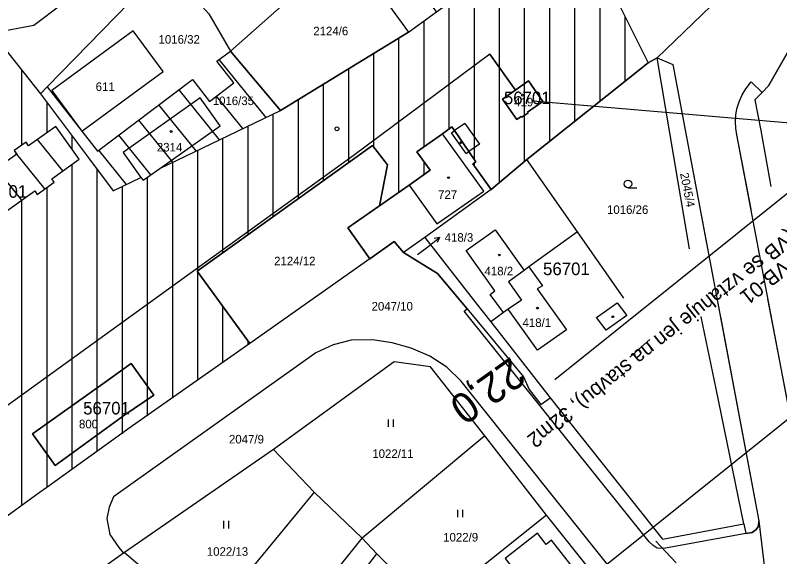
# Model space of a CAD drawing. Extents: x -794765 to -785424, y -1118958 to -1108731.
# Drawn here: x -792135.5 to -791983.5, y -1109804.8 to -1109697 of the extents above; entities that cross this region are included whole.
import ezdxf

# ---------------------------------------------------------------- set-up
doc = ezdxf.new("R2010")
doc.units = 0
for name, color, linetype in [('Level 66', 7, 'Continuous'), ('Level 71', 7, 'Continuous'), ('Level 73', 7, 'Continuous'), ('Level 75', 7, 'Continuous'), ('Level 76', 7, 'Continuous'), ('Level 77', 7, 'Continuous'), ('Level 78', 7, 'Continuous'), ('Level 79', 7, 'Continuous'), ('Level 80', 7, 'Continuous'), ('Level 81', 7, 'Continuous'), ('Vrstva 1', 7, 'Continuous'), ('Vrstva 53', 7, 'Continuous')]:
    doc.layers.add(name, color=color, linetype=linetype)

msp = doc.modelspace()

# ---------------------------------------------------------------- linework, layer by layer
at = {"layer": 'Level 66'}
for p, q in [((-792013.65, -1109731.34), (-792011.9, -1109731.34)), ((-792061.26, -1109778.93), (-792061.26, -1109777.43)), ((-792060.26, -1109778.93), (-792060.26, -1109777.43)), ((-792047.52, -1109796.9), (-792047.52, -1109795.4)), ((-792046.52, -1109796.9), (-792046.52, -1109795.4)), ((-792094.03, -1109799.12), (-792094.03, -1109797.62)), ((-792093.03, -1109799.12), (-792093.03, -1109797.62))]:
    msp.add_line(p, q, dxfattribs=at)
msp.add_circle((-792013.65, -1109730.59), 0.75, dxfattribs=at)
at = {"layer": 'Level 71'}
msp.add_lwpolyline([(-791938.08, -1109742.36), (-792598.01, -1110271.46), (-792786.15, -1110036.8), (-792126.22, -1109507.7)], close=True, dxfattribs=at)
at = {"layer": 'Level 75'}
for p, q in [((-792007.85, -1109705.47), (-791992.82, -1109691)), ((-791974.78, -1109691.82), (-791985.69, -1109711.05)), ((-792057.33, -1109700.37), (-792051.73, -1109696.36)), ((-792057.33, -1109700.37), (-792082.74, -1109715.97)), ((-792137.25, -1109704.07), (-792130.48, -1109712.65)), ((-792082.74, -1109715.97), (-792092.71, -1109704.13)), ((-792007.85, -1109705.47), (-792009.6, -1109706.46)), ((-792009.6, -1109706.46), (-792033.77, -1109725.73)), ((-791989.17, -1109710.28), (-791986.99, -1109712.39)), ((-792130.48, -1109712.65), (-792129.14, -1109711.27)), ((-791985.69, -1109711.05), (-791986.99, -1109712.39)), ((-792106.76, -1109727.49), (-792082.74, -1109715.97)), ((-791989.17, -1109735.63), (-791991.98, -1109720.83)), ((-792033.77, -1109725.73), (-792040.87, -1109731.66)), ((-792023.66, -1109740.13), (-792033.77, -1109725.73)), ((-792040.87, -1109731.66), (-792054.08, -1109741.21)), ((-792014.46, -1109753.3), (-792023.66, -1109740.13)), ((-792054.08, -1109741.21), (-792058.28, -1109744.24)), ((-792065.02, -1109745.49), (-792088.89, -1109762.3)), ((-791977.67, -1109796.24), (-791985.8, -1109753.42)), ((-791996.13, -1109771.37), (-791999.09, -1109757.03)), ((-792040.93, -1109758.03), (-792029.1, -1109773.17)), ((-792075.73, -1109764.16), (-792115.96, -1109792.85)), ((-791990.59, -1109798.22), (-791996.13, -1109771.37)), ((-792042.1, -1109780.72), (-792066.53, -1109801.07)), ((-792029.85, -1109796.46), (-792042.1, -1109780.72)), ((-792084.13, -1109783.45), (-792113.78, -1109803.9)), ((-792084.13, -1109783.45), (-792076.07, -1109791.91)), ((-792076.07, -1109791.91), (-792097.38, -1109817.76)), ((-792076.07, -1109791.91), (-792066.53, -1109801.07)), ((-792029.85, -1109796.46), (-792052.76, -1109814.79)), ((-792017.36, -1109812.14), (-792029.85, -1109796.46)), ((-791990.59, -1109798.22), (-791990.19, -1109800.13)), ((-791987.59, -1109797.65), (-791986.38, -1109808.14)), ((-791990.19, -1109800.13), (-792005.48, -1109802.95)), ((-792086.82, -1109826.3), (-792066.53, -1109801.07)), ((-792066.53, -1109801.07), (-792063.63, -1109804.17)), ((-792114.91, -1109802.94), (-792114.01, -1109804.07)), ((-792114.01, -1109804.07), (-792119.78, -1109808.18)), ((-792113.78, -1109803.9), (-792114.01, -1109804.07)), ((-792113.78, -1109803.9), (-792097.38, -1109817.76)), ((-792074.4, -1109818.02), (-792063.63, -1109804.17)), ((-792063.63, -1109804.17), (-792058.92, -1109808.77))]:
    msp.add_line(p, q, dxfattribs=at)
for points in [[(-792062.33, -1109677.36), (-792030.44, -1109685.15), (-792018.46, -1109688.78), (-792009.6, -1109706.46)], [(-792092.71, -1109704.13), (-792077.28, -1109690.45), (-792064.43, -1109679.2)], [(-792051.73, -1109696.36), (-792055.31, -1109691.31), (-792053.36, -1109689.93), (-792055.88, -1109686.41), (-792057.81, -1109687.78), (-792059.53, -1109685.37), (-792065.26, -1109689.44), (-792057.33, -1109700.37)], [(-792129.14, -1109711.27), (-792112.82, -1109694.46), (-792105.12, -1109689.46), (-792103.8, -1109689.27)], [(-792103.8, -1109689.27), (-792096.98, -1109696.76), (-792092.71, -1109704.13)], [(-792126.16, -1109694.83), (-792131.81, -1109699.06), (-792139.61, -1109700.53)], [(-792106.12, -1109708.23), (-792112.07, -1109700.09), (-792128.21, -1109711.96), (-792122.26, -1109720.08), (-792106.12, -1109708.23)], [(-792129.14, -1109711.27), (-792122.26, -1109720.08), (-792119.15, -1109724.06), (-792100.25, -1109709.81), (-792096.91, -1109714.15), (-792092.06, -1109710.49), (-792095.42, -1109706.17), (-792092.71, -1109704.13)], [(-792007.85, -1109705.47), (-792004.71, -1109706.83), (-791998.08, -1109742.02)], [(-792001.39, -1109743.48), (-792003.64, -1109730.21), (-792007.85, -1109705.47)], [(-792038.61, -1109713.71), (-792035.77, -1109717.77), (-792034.88, -1109717.16), (-792034.78, -1109717.31), (-792033.49, -1109716.43), (-792033.6, -1109716.27), (-792030.57, -1109714.17), (-792033.44, -1109710.08), (-792038.61, -1109713.71)], [(-791991.98, -1109720.83), (-791992.2, -1109719.5), (-791992.26, -1109718.2), (-791992.18, -1109716.87), (-791991.97, -1109715.65), (-791991.56, -1109714.23), (-791990.95, -1109712.85), (-791990.23, -1109711.63), (-791989.17, -1109710.28)], [(-792130.48, -1109712.65), (-792120.92, -1109725.39), (-792116.05, -1109731.95), (-792110.51, -1109729.29)], [(-792106.76, -1109727.49), (-792094.78, -1109719), (-792098.73, -1109713.45), (-792114.05, -1109724.35), (-792110.51, -1109729.29)], [(-791986.99, -1109712.39), (-791988.4, -1109713.84), (-791987.24, -1109719.97), (-791985.22, -1109731.09)], [(-792139.92, -1109727.96), (-792140.61, -1109726.97), (-792144.91, -1109730.01), (-792144.21, -1109731), (-792159.76, -1109741.99), (-792155.1, -1109748.67), (-792131.63, -1109731.96), (-792131.14, -1109732.66), (-792127.76, -1109730.25), (-792128.26, -1109729.56), (-792122.8, -1109725.68), (-792127.44, -1109719.13), (-792132.86, -1109722.97), (-792133.35, -1109722.27), (-792135.73, -1109723.95), (-792135.23, -1109724.65), (-792139.92, -1109727.96)], [(-792040.87, -1109731.66), (-792044.51, -1109726.58), (-792043.88, -1109726.16), (-792045.28, -1109724.14), (-792048.16, -1109719.98), (-792048.66, -1109719.25), (-792050.55, -1109720.58), (-792055.65, -1109724.16), (-792052.97, -1109727.83), (-792057.17, -1109730.8), (-792063.04, -1109734.91)], [(-792088.89, -1109762.3), (-792099.3, -1109747.92), (-792064.44, -1109722.94), (-792061.45, -1109726.78), (-792063.04, -1109734.91)], [(-792110.51, -1109729.29), (-792110.1, -1109729.86), (-792106.76, -1109727.49)], [(-792063.04, -1109734.91), (-792069.34, -1109739.32), (-792065.02, -1109745.49)], [(-792023.66, -1109740.13), (-792033.34, -1109747.1), (-792034.31, -1109747.79), (-792037.43, -1109750.08), (-792034.83, -1109753.69), (-792037.49, -1109755.5), (-792038.39, -1109756.14), (-792040.93, -1109758.03)], [(-792065.02, -1109745.49), (-792060.13, -1109742.03), (-792058.28, -1109744.24)], [(-792054.08, -1109741.21), (-792043.97, -1109754.14), (-792040.93, -1109758.03)], [(-792058.28, -1109744.24), (-792051.53, -1109748.38), (-792045.65, -1109755.46)], [(-792009.45, -1109801.79), (-792046.24, -1109755.92), (-792045.65, -1109755.46)], [(-792045.65, -1109755.46), (-792034.44, -1109768.97), (-792033.33, -1109771.51), (-792031.01, -1109774.5), (-792029.1, -1109773.17)], [(-791999.09, -1109757.03), (-791999.1, -1109756.95)], [(-791995.24, -1109757.05), (-791987.59, -1109797.65)], [(-791975.42, -1109863.21), (-791978.21, -1109857.78), (-791981.04, -1109853.58), (-792018.21, -1109805.69), (-792044.53, -1109772.76), (-792046.81, -1109769.82), (-792049.7, -1109767.06), (-792053.05, -1109764.88), (-792056.76, -1109763.28), (-792060.56, -1109762.21), (-792064.43, -1109761.57), (-792068.68, -1109761.68), (-792072.28, -1109762.62), (-792075.73, -1109764.16)], [(-792088.89, -1109762.3), (-792112.22, -1109778.74), (-792129.24, -1109790.96), (-792130.77, -1109792.06), (-792139.4, -1109798.31)], [(-792107.96, -1109772.62), (-792112.43, -1109766.33), (-792118.07, -1109770.33), (-792132.11, -1109780.3), (-792127.56, -1109786.58), (-792113.69, -1109776.53), (-792107.96, -1109772.62)], [(-792042.1, -1109780.72), (-792052.95, -1109766.96), (-792060.13, -1109766.01), (-792084.13, -1109783.45)], [(-792029.1, -1109773.17), (-792006.8, -1109801.29), (-791990.59, -1109798.22)], [(-792115.96, -1109792.85), (-792116.86, -1109794.88), (-792117.31, -1109797.12), (-792116.69, -1109800.34), (-792114.91, -1109802.94)], [(-791990.19, -1109800.13), (-791988.96, -1109799.96), (-791988.12, -1109799.35), (-791987.66, -1109798.67), (-791987.59, -1109797.65)], [(-792029.87, -1109815.6), (-792022.38, -1109809.77), (-792028.86, -1109801.47), (-792029.92, -1109802.3), (-792031.64, -1109800.09), (-792038.08, -1109805.1), (-792036.35, -1109807.31), (-792029.87, -1109815.6)], [(-792005.48, -1109802.95), (-792006.59, -1109803.15), (-792007.84, -1109803.07), (-792008.67, -1109802.54), (-792009.45, -1109801.79)]]:
    msp.add_lwpolyline(points, dxfattribs=at)
at = {"layer": 'Level 77'}
for p, q in [((-792046.11, -1109718.56), (-792048.16, -1109719.98)), ((-792046.11, -1109718.56), (-792043.21, -1109722.69)), ((-792042.35, -1109732.05), (-792050.55, -1109720.58)), ((-792048.75, -1109720.39), (-792048.16, -1109719.98)), ((-792045.84, -1109724.54), (-792048.75, -1109720.39)), ((-792043.21, -1109722.69), (-792045.28, -1109724.14)), ((-792045.84, -1109724.54), (-792045.28, -1109724.14)), ((-792057.17, -1109730.8), (-792051.69, -1109738.52)), ((-792051.69, -1109738.52), (-792042.35, -1109732.05)), ((-792045.81, -1109743.8), (-792040.07, -1109739.73)), ((-792040.07, -1109739.73), (-792034.31, -1109747.79)), ((-792040.1, -1109751.84), (-792045.81, -1109743.8)), ((-792033.34, -1109747.1), (-792030.63, -1109750.85)), ((-792030.63, -1109750.85), (-792031.74, -1109751.44)), ((-792031.74, -1109751.44), (-792025.88, -1109759.58)), ((-792041.08, -1109752.55), (-792040.1, -1109751.84)), ((-792038.39, -1109756.14), (-792041.08, -1109752.55)), ((-792019.89, -1109757.19), (-792015.77, -1109754.24)), ((-792015.77, -1109754.24), (-792013.86, -1109756.74)), ((-792031.67, -1109763.67), (-792037.49, -1109755.5)), ((-792017.98, -1109759.69), (-792019.89, -1109757.19)), ((-792013.86, -1109756.74), (-792017.98, -1109759.69)), ((-792025.88, -1109759.58), (-792031.67, -1109763.67)), ((-792009.29, -1109761.55), (-792013.29, -1109765.08))]:
    msp.add_line(p, q, dxfattribs=at)
at = {"layer": 'Level 78'}
for p, q in [((-792034.2, -1109726.09), (-792034.2, -1109684.23)), ((-792029.2, -1109722.09), (-792029.2, -1109685.53)), ((-792039.2, -1109730.27), (-792039.2, -1109687.2)), ((-792024.2, -1109718.1), (-792024.2, -1109687.04)), ((-792019.2, -1109714.11), (-792019.2, -1109688.56)), ((-792044.2, -1109725.7), (-792044.2, -1109690.83)), ((-792049.2, -1109719.63), (-792049.2, -1109694.47)), ((-792054.2, -1109723.14), (-792054.2, -1109698.1)), ((-792014.2, -1109710.13), (-792014.2, -1109697.28)), ((-792059.2, -1109732.22), (-792059.2, -1109701.52)), ((-792085.61, -1109717.35), (-792094.95, -1109705.82)), ((-792064.2, -1109723.25), (-792064.2, -1109704.59)), ((-792134.2, -1109722.87), (-792134.2, -1109707.94)), ((-792069.2, -1109726.35), (-792069.2, -1109707.66)), ((-792094.88, -1109721.79), (-792102.94, -1109711.84)), ((-792074.2, -1109729.93), (-792074.2, -1109710.73)), ((-792090.25, -1109719.57), (-792095.5, -1109713.09)), ((-792129.2, -1109720.38), (-792129.2, -1109714.36)), ((-792099.52, -1109724.02), (-792106.94, -1109714.85)), ((-792079.2, -1109733.52), (-792079.2, -1109713.8)), ((-792084.2, -1109737.1), (-792084.2, -1109716.67)), ((-792104.15, -1109726.24), (-792110.93, -1109717.86)), ((-792089.2, -1109740.68), (-792089.2, -1109719.07)), ((-792124.2, -1109723.7), (-792124.2, -1109721.02)), ((-792108.55, -1109728.76), (-792114.93, -1109720.88)), ((-792126.06, -1109727.99), (-792131.12, -1109721.74)), ((-792094.2, -1109744.27), (-792094.2, -1109721.47)), ((-792113.42, -1109730.69), (-792118.92, -1109723.89)), ((-792099.2, -1109747.85), (-792099.2, -1109723.86)), ((-792129.6, -1109731.56), (-792135.46, -1109724.32)), ((-792124.2, -1109787.39), (-792124.2, -1109726.67)), ((-792104.2, -1109773.18), (-792104.2, -1109726.26)), ((-792054.2, -1109728.7), (-792054.2, -1109726.15)), ((-792044.2, -1109727.01), (-792044.2, -1109726.37)), ((-792134.22, -1109733.8), (-792139.3, -1109727.53)), ((-792119.2, -1109783.84), (-792119.2, -1109727.71)), ((-792109.2, -1109776.73), (-792109.2, -1109729.22)), ((-792129.2, -1109790.94), (-792129.2, -1109731.28)), ((-792114.2, -1109780.29), (-792114.2, -1109731.06)), ((-792134.2, -1109794.54), (-792134.2, -1109733.79)), ((-792099.2, -1109769.63), (-792099.2, -1109748.06)), ((-792094.2, -1109766.07), (-792094.2, -1109754.96)), ((-792089.2, -1109762.52), (-792089.2, -1109761.87))]:
    msp.add_line(p, q, dxfattribs=at)
at = {"layer": 'Level 79'}
for centre in [(-792034.61, -1109712.91), (-792104.52, -1109720.15), (-792046.93, -1109722.38), (-792049.34, -1109729.33), (-792039.24, -1109744.72), (-792031.65, -1109755.29), (-792016.65, -1109757.01), (-792121.05, -1109774.88)]:
    msp.add_circle(centre, 0.175, dxfattribs=at)
at = {"layer": 'Level 80'}
for p, q in [((-792053.48, -1109743.08), (-792051.11, -1109741.23)), ((-792051.11, -1109741.23), (-792052.21, -1109741.45)), ((-792051.11, -1109741.23), (-792051.6, -1109742.24)), ((-792055.48, -1109744.64), (-792053.48, -1109743.08)), ((-792008.12, -1109801.63), (-792006.11, -1109803.8)), ((-792006.11, -1109803.8), (-792004.06, -1109806))]:
    msp.add_line(p, q, dxfattribs=at)
at = {"layer": 'Level 81'}
for points in [[(-791977.67, -1109796.24), (-791991.98, -1109720.83), (-791992.2, -1109719.5), (-791992.26, -1109718.2), (-791992.18, -1109716.87), (-791991.97, -1109715.65), (-791991.56, -1109714.23), (-791990.95, -1109712.85), (-791990.23, -1109711.63), (-791989.17, -1109710.28), (-791986.99, -1109712.39), (-791985.69, -1109711.05), (-791974.78, -1109691.82), (-791964.15, -1109675.11), (-791952.08, -1109657.83), (-791949.02, -1109652.63), (-791945.89, -1109647.32), (-791945.08, -1109645.94)], [(-792227.74, -1109767.63), (-792215.1, -1109759.26), (-792190.07, -1109741.13), (-792187.8, -1109739.49), (-792182.21, -1109735.57), (-792171.12, -1109727.8), (-792170.01, -1109729.04), (-792158.73, -1109719.12), (-792137.25, -1109704.07), (-792130.48, -1109712.65), (-792120.92, -1109725.39), (-792116.05, -1109731.95), (-792110.51, -1109729.29), (-792110.1, -1109729.86), (-792106.76, -1109727.49), (-792082.74, -1109715.97), (-792092.71, -1109704.13), (-792077.28, -1109690.45)], [(-792014.8, -1109810.08), (-792018.21, -1109805.69), (-792044.53, -1109772.76), (-792046.81, -1109769.82), (-792049.7, -1109767.06), (-792053.05, -1109764.88), (-792056.76, -1109763.28), (-792060.56, -1109762.21), (-792064.43, -1109761.57), (-792068.68, -1109761.68), (-792072.28, -1109762.62), (-792075.73, -1109764.16), (-792115.96, -1109792.85), (-792116.86, -1109794.88), (-792117.31, -1109797.12), (-792116.69, -1109800.34), (-792114.91, -1109802.94), (-792114.01, -1109804.07), (-792119.78, -1109808.18), (-792120.9, -1109806.8), (-792147.85, -1109825.45)]]:
    msp.add_lwpolyline(points, dxfattribs=at)
for points in [[(-792057.33, -1109700.37), (-792051.73, -1109696.36), (-792055.31, -1109691.31), (-792053.36, -1109689.93), (-792055.88, -1109686.41), (-792057.81, -1109687.78), (-792059.53, -1109685.37), (-792065.26, -1109689.44)], [(-792007.85, -1109705.47), (-792004.71, -1109706.83), (-791987.59, -1109797.65), (-791987.66, -1109798.67), (-791988.12, -1109799.35), (-791988.96, -1109799.96), (-791990.19, -1109800.13), (-792005.48, -1109802.95), (-792006.59, -1109803.15), (-792007.84, -1109803.07), (-792008.67, -1109802.54), (-792009.45, -1109801.79), (-792046.24, -1109755.92), (-792045.65, -1109755.46), (-792051.53, -1109748.38), (-792058.28, -1109744.24), (-792060.13, -1109742.03), (-792065.02, -1109745.49), (-792069.34, -1109739.32), (-792057.17, -1109730.8), (-792052.97, -1109727.83), (-792055.65, -1109724.16), (-792050.55, -1109720.58), (-792048.66, -1109719.25), (-792048.16, -1109719.98), (-792045.28, -1109724.14), (-792043.88, -1109726.16), (-792044.51, -1109726.58), (-792040.87, -1109731.66), (-792033.77, -1109725.73), (-792009.6, -1109706.46)], [(-792033.44, -1109710.08), (-792030.57, -1109714.17), (-792033.6, -1109716.27), (-792033.49, -1109716.43), (-792034.78, -1109717.31), (-792034.88, -1109717.16), (-792035.77, -1109717.77), (-792038.61, -1109713.71)], [(-792144.91, -1109730.01), (-792144.21, -1109731), (-792159.76, -1109741.99), (-792155.1, -1109748.67), (-792131.63, -1109731.96), (-792131.14, -1109732.66), (-792127.76, -1109730.25), (-792128.26, -1109729.56), (-792122.8, -1109725.68), (-792127.44, -1109719.13), (-792132.86, -1109722.97), (-792133.35, -1109722.27), (-792135.73, -1109723.95), (-792135.23, -1109724.65), (-792139.92, -1109727.96), (-792140.61, -1109726.97)], [(-792118.07, -1109770.33), (-792112.43, -1109766.33), (-792107.96, -1109772.62), (-792113.69, -1109776.53), (-792127.56, -1109786.58), (-792132.11, -1109780.3)]]:
    msp.add_lwpolyline(points, close=True, dxfattribs=at)
at = {"layer": 'Vrstva 1'}
for p, q in [((-792041.12, -1109704.75), (-792068.33, -1109725.02)), ((-792041.12, -1109704.75), (-792036.03, -1109711.9)), ((-791966.17, -1109719.81), (-792032.55, -1109714.08)), ((-791966.17, -1109719.81), (-792028.19, -1109769.53)), ((-792068.33, -1109725.02), (-792087.87, -1109739.13)), ((-792087.87, -1109739.13), (-792101.91, -1109749.26))]:
    msp.add_line(p, q, dxfattribs=at)
msp.add_lwpolyline([(-792036.03, -1109711.9), (-792041.12, -1109704.75), (-792068.33, -1109725.02), (-792101.91, -1109749.26), (-792182.09, -1109807.15)], dxfattribs=at)
msp.add_circle((-792071.53, -1109719.62), 0.375, dxfattribs=at)
at = {"layer": 'Vrstva 53'}
for points in [[(-792038.26, -1109686.52), (-792064.43, -1109679.2), (-792062.33, -1109677.36), (-792030.44, -1109685.15), (-792018.46, -1109688.78), (-792009.6, -1109706.46)], [(-792226.53, -1109766.83), (-792215.1, -1109759.26), (-792190.07, -1109741.13), (-792187.8, -1109739.49), (-792182.21, -1109735.57), (-792171.12, -1109727.8), (-792158.73, -1109719.12), (-792137.25, -1109704.07), (-792130.48, -1109712.65), (-792129.14, -1109711.27), (-792119.15, -1109724.06), (-792100.25, -1109709.81), (-792096.91, -1109714.15), (-792092.06, -1109710.49), (-792095.42, -1109706.17), (-792092.71, -1109704.13), (-792082.74, -1109715.97), (-792057.33, -1109700.37), (-792051.73, -1109696.36), (-792038.26, -1109686.52)], [(-792009.6, -1109706.46), (-792033.77, -1109725.73), (-792040.87, -1109731.66), (-792044.51, -1109726.58), (-792043.88, -1109726.16), (-792045.28, -1109724.14), (-792048.16, -1109719.98), (-792048.66, -1109719.25), (-792050.55, -1109720.58), (-792055.65, -1109724.16), (-792052.97, -1109727.83), (-792057.17, -1109730.8), (-792063.04, -1109734.91), (-792061.45, -1109726.78), (-792064.44, -1109722.94), (-792099.3, -1109747.92), (-792088.89, -1109762.3), (-792112.22, -1109778.74), (-792129.24, -1109790.96), (-792130.77, -1109792.06), (-792139.4, -1109798.31)]]:
    msp.add_lwpolyline(points, dxfattribs=at)

# ---------------------------------------------------------------- texts
at = {"layer": 'Level 73'}
msp.add_text('22,0', height=6, rotation=215.4038, dxfattribs=at).set_placement((-792036.89, -1109764.83))
at = {"layer": 'Level 76'}
for s, p in [('2124/6', (-792076.24, -1109701)), ('1016/32', (-792107.01, -1109702.67)), ('611', (-792119.52, -1109712.08)), ('1016/35', (-792096.24, -1109714.89)), ('419', (-792036.29, -1109715.14)), ('2314', (-792107.35, -1109724.12)), ('727', (-792051.42, -1109733.56)), ('1016/26', (-792017.82, -1109736.55)), ('418/3', (-792050.11, -1109742.08)), ('2124/12', (-792084.02, -1109746.76)), ('418/2', (-792042.18, -1109748.77)), ('2047/10', (-792064.64, -1109755.77)), ('418/1', (-792034.62, -1109759.03)), ('800', (-792122.84, -1109779.21)), ('2047/9', (-792093.01, -1109782.22)), ('1022/11', (-792064.5, -1109785.1)), ('1022/9', (-792050.4, -1109801.73)), ('1022/13', (-792097.41, -1109804.57))]:
    msp.add_text(s, height=1.7, dxfattribs=at).set_placement(p)
msp.add_text('2045/4', height=1.7, rotation=281, dxfattribs=at).set_placement((-792003.3, -1109728.51))
at = {"layer": 'Level 81'}
for p in [(-792038.33, -1109714.7), (-792142.43, -1109733.33), (-792030.54, -1109748.72), (-792122.01, -1109776.45)]:
    msp.add_text('56701', height=2.5, dxfattribs=at).set_placement(p)
at = {"layer": 'Vrstva 1'}
for s, p in [('parc.č.st.419 (VB se vztahuje jen na stavbu), 32m2', (-791962.75, -1109724.68)), ('věcné břemeno VB-01', (-791960.34, -1109727.72))]:
    msp.add_text(s, height=3, rotation=218.3254, dxfattribs=at).set_placement(p)

doc.saveas('drawing.dxf')
